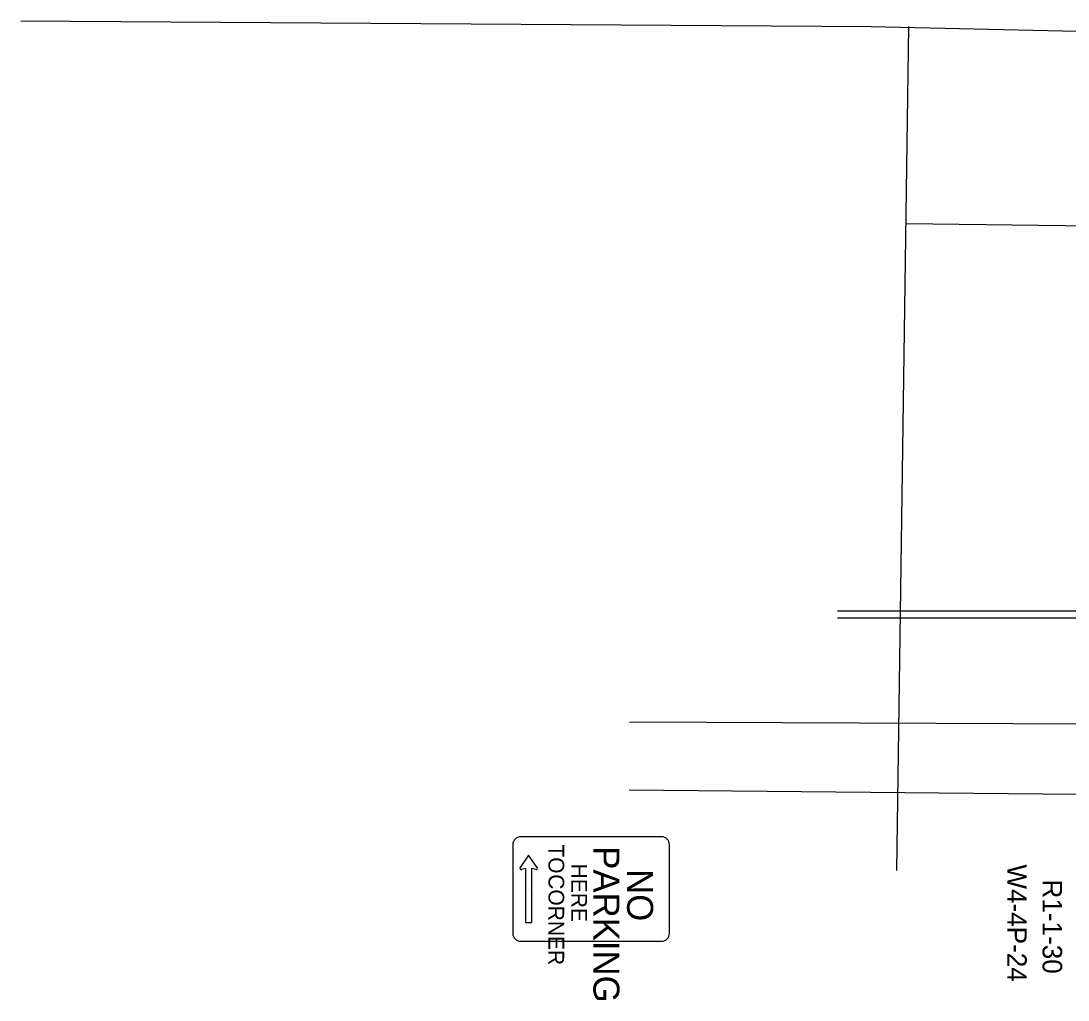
# Model space of a CAD drawing. Extents: x 108269 to 109415, y 548506 to 548874.
# Drawn here: x 108854.6 to 108929.7, y 548662.9 to 548733.2 of the extents above; entities that cross this region are included whole.
import ezdxf

# ---------------------------------------------------------------- set-up
doc = ezdxf.new("R2010")
doc.units = 0
for name, color, linetype in [('Default', 7, 'Continuous'), ('SN_P_Text', 7, 'Continuous'), ('SN_X_Public', 7, 'Continuous')]:
    doc.layers.add(name, color=color, linetype=linetype)

msp = doc.modelspace()

# ---------------------------------------------------------------- linework, layer by layer
at = {"layer": 'Default'}
for p, q in [((108854.55, 548733.19), (108915.584, 548732.793)), ((108915.584, 548732.793), (109082.359, 548728.905)), ((108917.441, 548672.204), (108918.296, 548732.802)), ((108918.097, 548718.652), (109208.222, 548714.907)), ((108913.178, 548690.344), (108968.755, 548690.312)), ((108913.179, 548690.844), (108968.755, 548690.812))]:
    msp.add_line(p, q, dxfattribs=at)
for points in [[(108898.235, 548682.867), (108969.787, 548682.571), (108976.966, 548686.838)], [(108898.229, 548677.994), (108969.973, 548677.301), (108970.099, 548673.581), (108977.513, 548668.904)]]:
    msp.add_lwpolyline(points, dxfattribs=at)
at = {"layer": 'SN_X_Public'}
for p, q in [((108891.003, 548673.313), (108890.382, 548672.428)), ((108891.625, 548672.428), (108891.003, 548673.313)), ((108890.484, 548672.289), (108890.769, 548672.379)), ((108890.769, 548672.379), (108890.769, 548672.375)), ((108890.769, 548672.375), (108890.769, 548668.469)), ((108891.238, 548672.379), (108891.523, 548672.289)), ((108891.003, 548670.891), (108891.003, 548670.891)), ((108890.769, 548668.469), (108891.238, 548668.469))]:
    msp.add_line(p, q, dxfattribs=at)
for points in [[(108900.553, 548674.627), (108890.428, 548674.627)], [(108889.865, 548674.065), (108889.865, 548667.69)], [(108901.115, 548667.69), (108901.115, 548674.065)], [(108891.238, 548668.469), (108891.238, 548672.375)], [(108890.428, 548667.127), (108900.553, 548667.127)]]:
    msp.add_lwpolyline(points, dxfattribs=at)
for centre, radius, start, end in [((108890.428, 548674.065), 0.562, 90, 180), ((108900.553, 548674.065), 0.562, 360, 90), ((108890.456, 548672.375), 0.0912, 144.92075, 287.6378), ((108891.55, 548672.375), 0.0912, 252.3622, 35.07924), ((108890.428, 548667.69), 0.562, 180, 270), ((108900.553, 548667.69), 0.562, 270, 360)]:
    msp.add_arc(centre, radius, start, end, dxfattribs=at)

# ---------------------------------------------------------------- texts
at = {"layer": 'SN_P_Text'}
for s, p in [('W4-4P-24', (108925.363, 548672.645)), ('R1-1-30', (108927.904, 548671.558))]:
    msp.add_text(s, height=1.4, rotation=270, dxfattribs=at).set_placement(p)
at = {"layer": 'SN_X_Public'}
for s, height, p in [('TO', 1.125, (108892.428, 548674.076)), ('PARKING', 1.8656, (108895.651, 548673.947)), ('HERE', 1.125, (108894.069, 548672.695)), ('CORNER', 1.125, (108892.428, 548671.934)), ('NO', 1.8656, (108898.073, 548672.305))]:
    msp.add_text(s, height=height, rotation=270, dxfattribs=at).set_placement(p)

doc.saveas('drawing.dxf')
